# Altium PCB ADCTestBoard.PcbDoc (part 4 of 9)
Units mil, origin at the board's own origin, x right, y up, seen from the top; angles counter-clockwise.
Board outline 11022.62 x 9187 mil, 8 copper layers (TopLayer, InternalPlane1, InternalPlane2, InternalPlane3, InternalPlane4, InternalPlane5, MidLayer1, BottomLayer), stack 103.8 mil thick; 1282 components, 637 nets, 4473 pads, 1306 vias.
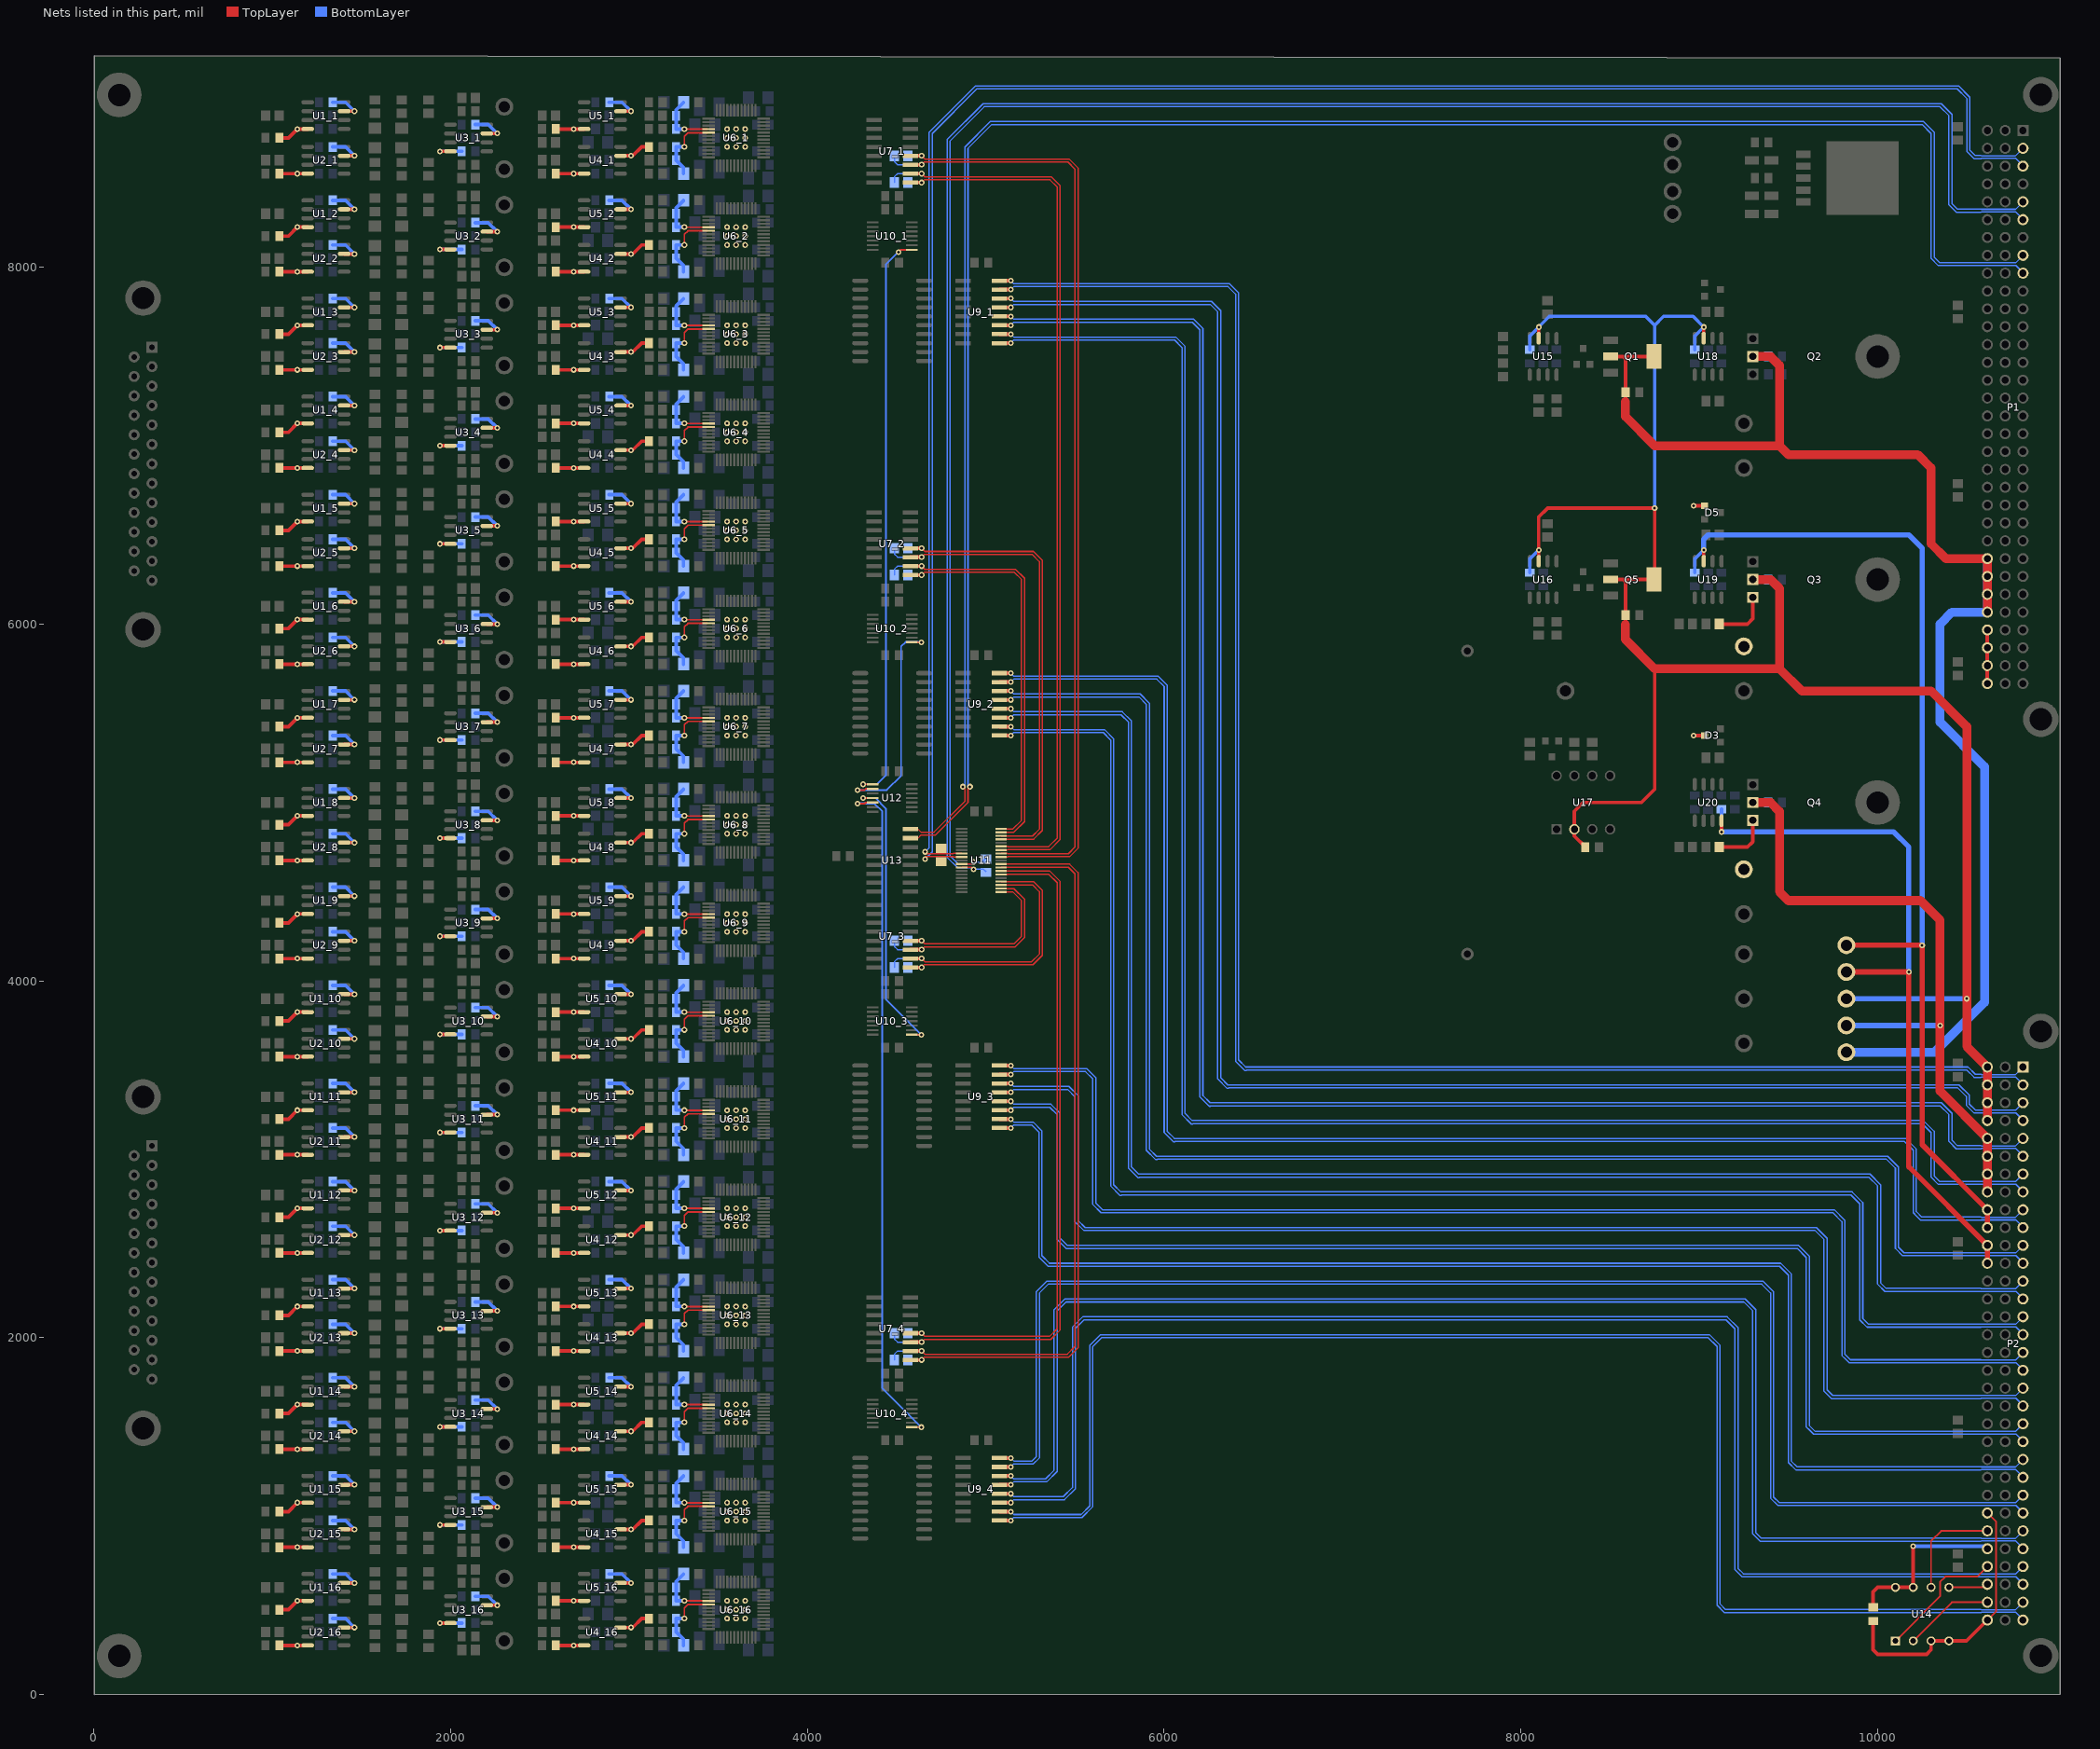
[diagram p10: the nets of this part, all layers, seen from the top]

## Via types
v1: diameter 32, hole 16, TopLayer to BottomLayer, 1306 vias

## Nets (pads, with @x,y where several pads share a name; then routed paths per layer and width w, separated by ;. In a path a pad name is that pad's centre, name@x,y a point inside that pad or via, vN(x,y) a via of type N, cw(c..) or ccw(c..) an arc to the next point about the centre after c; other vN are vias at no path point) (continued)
+15V: C1_1.1 C1_2.1 C1_3.1 C1_4.1 C1_5.1 C1_6.1 C1_7.1 C1_8.1 C1_9.1 C1_10.1 C1_11.1 C1_12.1 C1_13.1 C1_14.1 C1_15.1 C1_16.1 C3_1.1 C3_2.1 C3_3.1 C3_4.1 C3_5.1 C3_6.1 C3_7.1 C3_8.1 C3_9.1 C3_10.1 C3_11.1 C3_12.1 C3_13.1 C3_14.1 C3_15.1 C3_16.1 C19_1.1 C19_2.1 C19_3.1 C19_4.1 C19_5.1 C19_6.1 C19_7.1 C19_8.1 C19_9.1 C19_10.1 C19_11.1 C19_12.1 C19_13.1 C19_14.1 C19_15.1 C19_16.1 C20_1.2 C20_2.2 C20_3.2 C20_4.2 C20_5.2 C20_6.2 C20_7.2 C20_8.2 C20_9.2 C20_10.2 C20_11.2 C20_12.2 C20_13.2 C20_14.2 C20_15.2 C20_16.2 C21_1.2 C21_2.2 C21_3.2 C21_4.2 C21_5.2 C21_6.2 C21_7.2 C21_8.2 C21_9.2 C21_10.2 C21_11.2 C21_12.2 C21_13.2 C21_14.2 C21_15.2 C21_16.2 C22_1.2 C22_2.2 C22_3.2 C22_4.2 C22_5.2 C22_6.2 C22_7.2 C22_8.2 C22_9.2 C22_10.2 C22_11.2 C22_12.2 C22_13.2 C22_14.2 C22_15.2 C22_16.2 C29_1.1 C29_2.1 C29_3.1 C29_4.1 C29_5.1 C29_6.1 C29_7.1 C29_8.1 C29_9.1 C29_10.1 C29_11.1 C29_12.1 C29_13.1 C29_14.1 C29_15.1 C29_16.1 C38_1.1 C38_2.1 C38_3.1 C38_4.1 C38_5.1 C38_6.1 C38_7.1 C38_8.1 C38_9.1 C38_10.1 C38_11.1 C38_12.1 C38_13.1 C38_14.1 C38_15.1 C38_16.1 D5.1 Q3.3 R44.2 TP12.1 U1_1.7 U1_2.7 U1_3.7 U1_4.7 U1_5.7 U1_6.7 U1_7.7 U1_8.7 U1_9.7 U1_10.7 U1_11.7 U1_12.7 U1_13.7 U1_14.7 U1_15.7 U1_16.7 U2_1.7 U2_2.7 U2_3.7 U2_4.7 U2_5.7 U2_6.7 U2_7.7 U2_8.7 U2_9.7 U2_10.7 U2_11.7 U2_12.7 U2_13.7 U2_14.7 U2_15.7 U2_16.7 U3_1.7 U3_2.7 U3_3.7 U3_4.7 U3_5.7 U3_6.7 U3_7.7 U3_8.7 U3_9.7 U3_10.7 U3_11.7 U3_12.7 U3_13.7 U3_14.7 U3_15.7 U3_16.7 U4_1.7 U4_2.7 U4_3.7 U4_4.7 U4_5.7 U4_6.7 U4_7.7 U4_8.7 U4_9.7 U4_10.7 U4_11.7 U4_12.7 U4_13.7 U4_14.7 U4_15.7 U4_16.7 U5_1.7 U5_2.7 U5_3.7 U5_4.7 U5_5.7 U5_6.7 U5_7.7 U5_8.7 U5_9.7 U5_10.7 U5_11.7 U5_12.7 U5_13.7 U5_14.7 U5_15.7 U5_16.7 U6_1.40 U6_2.40 U6_3.40 U6_4.40 U6_5.40 U6_6.40 U6_7.40 U6_8.40 U6_9.40 U6_10.40 U6_11.40 U6_12.40 U6_13.40 U6_14.40 U6_15.40 U6_16.40 | length 21497.4
  TopLayer w10: v1(3310,525) 3310.79,524.21 U6_16.40@3435.63,524.21 ; v1(3310,1075) 3310.79,1074.21 U6_15.40@3435.63,1074.21 ; v1(3310,1625) 3310.79,1624.21 U6_14.40@3435.63,1624.21 ; v1(3310,2175) 3310.79,2174.21 U6_13.40@3435.63,2174.21 ; v1(3310,2725) 3310.79,2724.21 U6_12.40@3435.63,2724.21 ; v1(3310,3275) 3310.79,3274.21 U6_11.40@3435.63,3274.21 ; v1(3310,3825) 3310.79,3824.21 U6_10.40@3435.63,3824.21 ; v1(3310,4375) 3310.79,4374.21 U6_9.40@3435.63,4374.21 ; v1(3310,4925) 3310.79,4924.21 U6_8.40@3435.63,4924.21 ; v1(3310,5475) 3310.79,5474.21 U6_7.40@3435.63,5474.21 ; v1(3310,6025) 3310.79,6024.21 U6_6.40@3435.63,6024.21 ; v1(3310,6575) 3310.79,6574.21 U6_5.40@3435.63,6574.21 ; v1(3310,7125) 3310.79,7124.21 U6_4.40@3435.63,7124.21 ; v1(3310,7675) 3310.79,7674.21 U6_3.40@3435.63,7674.21 ; v1(3310,8225) 3310.79,8224.21 U6_2.40@3435.63,8224.21 ; v1(3310,8775) 3310.79,8774.21 U6_1.40@3435.63,8774.21
  TopLayer w20: U2_16.7@1402.36,375 v1(1460,375) ; U1_16.7@1402.36,625 v1(1460,625) ; U2_15.7@1402.36,925 v1(1460,925) ; U1_15.7@1402.36,1175 v1(1460,1175) ; U2_14.7@1402.36,1475 v1(1460,1475) ; U1_14.7@1402.36,1725 v1(1460,1725) ; U2_13.7@1402.36,2025 v1(1460,2025) ; U1_13.7@1402.36,2275 v1(1460,2275) ; U2_12.7@1402.36,2575 v1(1460,2575) ; U1_12.7@1402.36,2825 v1(1460,2825) ; U2_11.7@1402.36,3125 v1(1460,3125) ; U1_11.7@1402.36,3375 v1(1460,3375) ; U2_10.7@1402.36,3675 v1(1460,3675) ; U1_10.7@1402.36,3925 v1(1460,3925) ; U2_9.7@1402.36,4225 v1(1460,4225) ; U1_9.7@1402.36,4475 v1(1460,4475) ; U2_8.7@1402.36,4775 v1(1460,4775) ; U1_8.7@1402.36,5025 v1(1460,5025) ; U2_7.7@1402.36,5325 v1(1460,5325) ; U1_7.7@1402.36,5575 v1(1460,5575) ; U2_6.7@1402.36,5875 v1(1460,5875) ; U1_6.7@1402.36,6125 v1(1460,6125) ; U2_5.7@1402.36,6425 v1(1460,6425) ; U1_5.7@1402.36,6675 v1(1460,6675) ; U2_4.7@1402.36,6975 v1(1460,6975) ; U1_4.7@1402.36,7225 v1(1460,7225) ; U2_3.7@1402.36,7525 v1(1460,7525) ; U1_3.7@1402.36,7775 v1(1460,7775) ; U2_2.7@1402.36,8075 v1(1460,8075) ; U1_2.7@1402.36,8325 v1(1460,8325) ; U2_1.7@1402.36,8625 v1(1460,8625) ; U1_1.7@1402.36,8875 v1(1460,8875) ; U3_16.7@2202.36,500 v1(2260,500) ; U3_15.7@2202.36,1050 v1(2260,1050) ; U3_14.7@2202.36,1600 v1(2260,1600) ; U3_13.7@2202.36,2150 v1(2260,2150) ; U3_12.7@2202.36,2700 v1(2260,2700) ; U3_11.7@2202.36,3250 v1(2260,3250) ; U3_10.7@2202.36,3800 v1(2260,3800) ; U3_9.7@2202.36,4350 v1(2260,4350) ; U3_8.7@2202.36,4900 v1(2260,4900) ; U3_7.7@2202.36,5450 v1(2260,5450) ; U3_6.7@2202.36,6000 v1(2260,6000) ; U3_5.7@2202.36,6550 v1(2260,6550) ; U3_4.7@2202.36,7100 v1(2260,7100) ; U3_3.7@2202.36,7650 v1(2260,7650) ; U3_2.7@2202.36,8200 v1(2260,8200) ; U3_1.7@2202.36,8750 v1(2260,8750) ; U4_16.7@2952.36,375 3020,375 3070,425 C38_16.1@3111.61,425 ; U5_16.7@2952.36,625 v1(3010,625) ; U4_15.7@2952.36,925 3020,925 3070,975 C38_15.1@3111.61,975 ; U5_15.7@2952.36,1175 v1(3010,1175) ; U4_14.7@2952.36,1475 3020,1475 3070,1525 C38_14.1@3111.61,1525 ; U5_14.7@2952.36,1725 v1(3010,1725) ; U4_13.7@2952.36,2025 3020,2025 3070,2075 C38_13.1@3111.61,2075 ; U5_13.7@2952.36,2275 v1(3010,2275) ; U4_12.7@2952.36,2575 3020,2575 3070,2625 C38_12.1@3111.61,2625 ; U5_12.7@2952.36,2825 v1(3010,2825) ; U4_11.7@2952.36,3125 3020,3125 3070,3175 C38_11.1@3111.61,3175 ; U5_11.7@2952.36,3375 v1(3010,3375) ; U4_10.7@2952.36,3675 3020,3675 3070,3725 C38_10.1@3111.61,3725 ; U5_10.7@2952.36,3925 v1(3010,3925) ; U4_9.7@2952.36,4225 3020,4225 3070,4275 C38_9.1@3111.61,4275 ; U5_9.7@2952.36,4475 v1(3010,4475) ; U4_8.7@2952.36,4775 3020,4775 3070,4825 C38_8.1@3111.61,4825 ; U5_8.7@2952.36,5025 v1(3010,5025) ; U4_7.7@2952.36,5325 3020,5325 3070,5375 C38_7.1@3111.61,5375 ; U5_7.7@2952.36,5575 v1(3010,5575) ; U4_6.7@2952.36,5875 3020,5875 3070,5925 C38_6.1@3111.61,5925 ; U5_6.7@2952.36,6125 v1(3010,6125) ; U4_5.7@2952.36,6425 3020,6425 3070,6475 C38_5.1@3111.61,6475 ; U5_5.7@2952.36,6675 v1(3010,6675) ; U4_4.7@2952.36,6975 3020,6975 3070,7025 C38_4.1@3111.61,7025 ; U5_4.7@2952.36,7225 v1(3010,7225) ; U4_3.7@2952.36,7525 3020,7525 3070,7575 C38_3.1@3111.61,7575 ; U5_3.7@2952.36,7775 v1(3010,7775) ; U4_2.7@2952.36,8075 3020,8075 3070,8125 C38_2.1@3111.61,8125 ; U5_2.7@2952.36,8325 v1(3010,8325) ; U4_1.7@2952.36,8625 3020,8625 3070,8675 C38_1.1@3111.61,8675 ; U5_1.7@2952.36,8875 v1(3010,8875) ; v1(8968.07,6662.4) D5.1@9030.71,6662.4 ; R44.2@9112.4,6000 9270,6000 9300,6030 Q3.3@9300,6150
  BottomLayer w20: C19_16.1@1338.39,425 1410,425 v1(1460,375) ; C1_16.1@1338.39,675 1410,675 v1(1460,625) ; C19_15.1@1338.39,975 1410,975 v1(1460,925) ; C1_15.1@1338.39,1225 1410,1225 v1(1460,1175) ; C19_14.1@1338.39,1525 1410,1525 v1(1460,1475) ; C1_14.1@1338.39,1775 1410,1775 v1(1460,1725) ; C19_13.1@1338.39,2075 1410,2075 v1(1460,2025) ; C1_13.1@1338.39,2325 1410,2325 v1(1460,2275) ; C19_12.1@1338.39,2625 1410,2625 v1(1460,2575) ; C1_12.1@1338.39,2875 1410,2875 v1(1460,2825) ; C19_11.1@1338.39,3175 1410,3175 v1(1460,3125) ; C1_11.1@1338.39,3425 1410,3425 v1(1460,3375) ; C19_10.1@1338.39,3725 1410,3725 v1(1460,3675) ; C1_10.1@1338.39,3975 1410,3975 v1(1460,3925) ; C19_9.1@1338.39,4275 1410,4275 v1(1460,4225) ; C1_9.1@1338.39,4525 1410,4525 v1(1460,4475) ; C19_8.1@1338.39,4825 1410,4825 v1(1460,4775) ; C1_8.1@1338.39,5075 1410,5075 v1(1460,5025) ; C19_7.1@1338.39,5375 1410,5375 v1(1460,5325) ; C1_7.1@1338.39,5625 1410,5625 v1(1460,5575) ; C19_6.1@1338.39,5925 1410,5925 v1(1460,5875) ; C1_6.1@1338.39,6175 1410,6175 v1(1460,6125) ; C19_5.1@1338.39,6475 1410,6475 v1(1460,6425) ; C1_5.1@1338.39,6725 1410,6725 v1(1460,6675) ; C19_4.1@1338.39,7025 1410,7025 v1(1460,6975) ; C1_4.1@1338.39,7275 1410,7275 v1(1460,7225) ; C19_3.1@1338.39,7575 1410,7575 v1(1460,7525) ; C1_3.1@1338.39,7825 1410,7825 v1(1460,7775) ; C19_2.1@1338.39,8125 1410,8125 v1(1460,8075) ; C1_2.1@1338.39,8375 1410,8375 v1(1460,8325) ; C19_1.1@1338.39,8675 1410,8675 v1(1460,8625) ; C1_1.1@1338.39,8925 1410,8925 v1(1460,8875) ; C3_16.1@2138.39,550 2210,550 v1(2260,500) ; C3_15.1@2138.39,1100 2210,1100 v1(2260,1050) ; C3_14.1@2138.39,1650 2210,1650 v1(2260,1600) ; C3_13.1@2138.39,2200 2210,2200 v1(2260,2150) ; C3_12.1@2138.39,2750 2210,2750 v1(2260,2700) ; C3_11.1@2138.39,3300 2210,3300 v1(2260,3250) ; C3_10.1@2138.39,3850 2210,3850 v1(2260,3800) ; C3_9.1@2138.39,4400 2210,4400 v1(2260,4350) ; C3_8.1@2138.39,4950 2210,4950 v1(2260,4900) ; C3_7.1@2138.39,5500 2210,5500 v1(2260,5450) ; C3_6.1@2138.39,6050 2210,6050 v1(2260,6000) ; C3_5.1@2138.39,6600 2210,6600 v1(2260,6550) ; C3_4.1@2138.39,7150 2210,7150 v1(2260,7100) ; C3_3.1@2138.39,7700 2210,7700 v1(2260,7650) ; C3_2.1@2138.39,8250 2210,8250 v1(2260,8200) ; C3_1.1@2138.39,8800 2210,8800 v1(2260,8750) ; C29_16.1@2888.39,675 2960,675 v1(3010,625) ; C29_15.1@2888.39,1225 2960,1225 v1(3010,1175) ; C29_14.1@2888.39,1775 2960,1775 v1(3010,1725) ; C29_13.1@2888.39,2325 2960,2325 v1(3010,2275) ; C29_12.1@2888.39,2875 2960,2875 v1(3010,2825) ; C29_11.1@2888.39,3425 2960,3425 v1(3010,3375) ; C29_10.1@2888.39,3975 2960,3975 v1(3010,3925) ; C29_9.1@2888.39,4525 2960,4525 v1(3010,4475) ; C29_8.1@2888.39,5075 2960,5075 v1(3010,5025) ; C29_7.1@2888.39,5625 2960,5625 v1(3010,5575) ; C29_6.1@2888.39,6175 2960,6175 v1(3010,6125) ; C29_5.1@2888.39,6725 2960,6725 v1(3010,6675) ; C29_4.1@2888.39,7275 2960,7275 v1(3010,7225) ; C29_3.1@2888.39,7825 2960,7825 v1(3010,7775) ; C29_2.1@2888.39,8375 2960,8375 v1(3010,8325) ; C29_1.1@2888.39,8925 2960,8925 v1(3010,8875) ; C20_16.2@3305.12,675 3263.39,633.27 C21_16.2@3263.39,525 v1(3310,525) ; C20_15.2@3305.12,1225 3263.39,1183.27 C21_15.2@3263.39,1075 v1(3310,1075) ; C20_14.2@3305.12,1775 3263.39,1733.27 C21_14.2@3263.39,1625 v1(3310,1625) ; C20_13.2@3305.12,2325 3263.39,2283.27 C21_13.2@3263.39,2175 v1(3310,2175) ; C20_12.2@3305.12,2875 3263.39,2833.27 C21_12.2@3263.39,2725 v1(3310,2725) ; C20_11.2@3305.12,3425 3263.39,3383.27 C21_11.2@3263.39,3275 v1(3310,3275) ; C20_10.2@3305.12,3975 3263.39,3933.27 C21_10.2@3263.39,3825 v1(3310,3825) ; C20_9.2@3305.12,4525 3263.39,4483.27 C21_9.2@3263.39,4375 v1(3310,4375) ; C20_8.2@3305.12,5075 3263.39,5033.27 C21_8.2@3263.39,4925 v1(3310,4925) ; C20_7.2@3305.12,5625 3263.39,5583.27 C21_7.2@3263.39,5475 v1(3310,5475) ; C20_6.2@3305.12,6175 3263.39,6133.27 C21_6.2@3263.39,6025 v1(3310,6025) ; C20_5.2@3305.12,6725 3263.39,6683.27 C21_5.2@3263.39,6575 v1(3310,6575) ; C20_4.2@3305.12,7275 3263.39,7233.27 C21_4.2@3263.39,7125 v1(3310,7125) ; C20_3.2@3305.12,7825 3263.39,7783.27 C21_3.2@3263.39,7675 v1(3310,7675) ; C20_2.2@3305.12,8375 3263.39,8333.27 C21_2.2@3263.39,8225 v1(3310,8225) ; C20_1.2@3305.12,8925 3263.39,8883.27 C21_1.2@3263.39,8775 v1(3310,8775)
  other v1: 3010,375 3010,925 3010,1475 3010,2025 3010,2575 3010,3125 3010,3675 3010,4225 3010,4775 3010,5325 3010,5875 3010,6425 3010,6975 3010,7525 3010,8075 3010,8625
+AV1: C47.2 C54.2 P1.25C P1.26C P1.27C P1.28C Q1.2 Q1.4 Q2.2 TP7.1 | length 7901.1
  TopLayer w20: Q1.2@8502.95,7500 8573.23,7500 8586.61,7486.61 ; 8586.61,7247.6 8586.61,7486.61 ; Q1.4@8747.05,7500 8600,7500 8586.61,7486.61
  TopLayer w50: 8586.61,7247.6 8586.61,7163.39 8750,7000 9450,7000 ; Q2.2@9300,7500 9400,7500 9450,7450 9450,7000 ; P1.28C@10615.41,6067 P1.25C@10615.41,6367 10383,6367 10300,6450 10300,6875 10225,6950 9500,6950 9450,7000
  BottomLayer w20: Q2.2@9300,7500 C54.2@9386.61,7500
  BottomLayer w50: TP7.1@9825,3600 10320,3600 10600,3880 10600,5200 10350,5450 10350,6000 10417,6067 P1.28C@10615.41,6067 P1.25C@10615.41,6367
+AV2: C49.1 C50.2 C52.2 C55.1 C59.2 C80.2 P2.1C P2.2C P2.3C P2.4C Q3.2 Q5.2 Q5.4 TP8.1 U15.7 U16.7 U17.2 U18.7 | length 11662.5
  TopLayer w20: U16.7@8100,6352.36 8100,6600 8150,6650 v1(8750,6650) 8750,6252.95 Q5.4@8747.05,6250 8600,6250 8586.61,6236.61 ; U15.7@8100,7602.36 v1(8100,7665) ; C52.2@8361.61,4750 8300,4811.61 8300,4950 8350,5000 8675,5000 8750,5075 8750,5750 ; Q5.2@8502.95,6250 8573.23,6250 8586.61,6236.61 ; 8586.61,5997.6 8586.61,6236.61 ; U18.7@9025,7602.36 v1(9025,7665)
  TopLayer w50: 8586.61,5997.6 8586.61,5913.39 8750,5750 9450,5750 ; Q3.2@9300,6250 9400,6250 9450,6200 9450,5750 ; P2.4C@10615.41,3217 P2.1C@10615.41,3517 10500,3632.41 10500,5425 10300,5625 9575,5625 9450,5750
  BottomLayer w20: C80.2@8050,6288.39 8050,6365 v1(8100,6415) ; C50.2@8050,7538.39 8050,7615 8160,7725 8700,7725 8750,7675 ; v1(8750,6650) 8750,7675 ; C59.2@8975,7538.39 8975,7615 v1(9025,7665) 8965,7725 8800,7725 8750,7675 ; Q3.2@9300,6250 C55.1@9386.61,6250
  BottomLayer w30: TP8.1@9825,3900 v1(10500,3900)
+AV3: C60.1 P2.9C P2.10C TP9.1 U19.7 | length 5920.7
  TopLayer w20: U19.7@9025,6352.36 v1(9025,6415)
  TopLayer w30: TP9.1@9825,4200 v1(10250,4200) 10250,3082.41 P2.9C@10615.41,2717 P2.10C@10615.41,2617
  BottomLayer w20: C60.1@8975,6288.39 8975,6365 v1(9025,6415)
  BottomLayer w30: v1(9025,6415) 9025,6475 9050,6500 10175,6500 10250,6425 v1(10250,4200)
-15V: C5_1.1 C5_2.1 C5_3.1 C5_4.1 C5_5.1 C5_6.1 C5_7.1 C5_8.1 C5_9.1 C5_10.1 C5_11.1 C5_12.1 C5_13.1 C5_14.1 C5_15.1 C5_16.1 C8_1.1 C8_2.1 C8_3.1 C8_4.1 C8_5.1 C8_6.1 C8_7.1 C8_8.1 C8_9.1 C8_10.1 C8_11.1 C8_12.1 C8_13.1 C8_14.1 C8_15.1 C8_16.1 C10_1.1 C10_2.1 C10_3.1 C10_4.1 C10_5.1 C10_6.1 C10_7.1 C10_8.1 C10_9.1 C10_10.1 C10_11.1 C10_12.1 C10_13.1 C10_14.1 C10_15.1 C10_16.1 C28_1.1 C28_2.1 C28_3.1 C28_4.1 C28_5.1 C28_6.1 C28_7.1 C28_8.1 C28_9.1 C28_10.1 C28_11.1 C28_12.1 C28_13.1 C28_14.1 C28_15.1 C28_16.1 C39_1.1 C39_2.1 C39_3.1 C39_4.1 C39_5.1 C39_6.1 C39_7.1 C39_8.1 C39_9.1 C39_10.1 C39_11.1 C39_12.1 C39_13.1 C39_14.1 C39_15.1 C39_16.1 C40_1.2 C40_2.2 C40_3.2 C40_4.2 C40_5.2 C40_6.2 C40_7.2 C40_8.2 C40_9.2 C40_10.2 C40_11.2 C40_12.2 C40_13.2 C40_14.2 C40_15.2 C40_16.2 C41_1.2 C41_2.2 C41_3.2 C41_4.2 C41_5.2 C41_6.2 C41_7.2 C41_8.2 C41_9.2 C41_10.2 C41_11.2 C41_12.2 C41_13.2 C41_14.2 C41_15.2 C41_16.2 C42_1.2 C42_2.2 C42_3.2 C42_4.2 C42_5.2 C42_6.2 C42_7.2 C42_8.2 C42_9.2 C42_10.2 C42_11.2 C42_12.2 C42_13.2 C42_14.2 C42_15.2 C42_16.2 D3.3 pad.0 Q4.3 R35.2 TP10.1 U1_1.4 U1_2.4 U1_3.4 U1_4.4 U1_5.4 U1_6.4 U1_7.4 U1_8.4 U1_9.4 U1_10.4 U1_11.4 U1_12.4 U1_13.4 U1_14.4 U1_15.4 U1_16.4 U2_1.4 U2_2.4 U2_3.4 U2_4.4 U2_5.4 U2_6.4 U2_7.4 U2_8.4 U2_9.4 U2_10.4 U2_11.4 U2_12.4 U2_13.4 U2_14.4 U2_15.4 U2_16.4 U3_1.4 U3_2.4 U3_3.4 U3_4.4 U3_5.4 U3_6.4 U3_7.4 U3_8.4 U3_9.4 U3_10.4 U3_11.4 U3_12.4 U3_13.4 U3_14.4 U3_15.4 U3_16.4 U4_1.4 U4_2.4 U4_3.4 U4_4.4 U4_5.4 U4_6.4 U4_7.4 U4_8.4 U4_9.4 U4_10.4 U4_11.4 U4_12.4 U4_13.4 U4_14.4 U4_15.4 U4_16.4 U5_1.4 U5_2.4 U5_3.4 U5_4.4 U5_5.4 U5_6.4 U5_7.4 U5_8.4 U5_9.4 U5_10.4 U5_11.4 U5_12.4 U5_13.4 U5_14.4 U5_15.4 U5_16.4 U6_1.41 U6_2.41 U6_3.41 U6_4.41 U6_5.41 U6_6.41 U6_7.41 U6_8.41 U6_9.41 U6_10.41 U6_11.41 U6_12.41 U6_13.41 U6_14.41 U6_15.41 U6_16.41 | length 20296.1
  TopLayer w10: v1(3310,425) 3310,485 3329.53,504.53 U6_16.41@3435.63,504.53 ; v1(3310,975) 3310,1035 3329.53,1054.53 U6_15.41@3435.63,1054.53 ; v1(3310,1525) 3310,1585 3329.53,1604.53 U6_14.41@3435.63,1604.53 ; v1(3310,2075) 3310,2135 3329.53,2154.53 U6_13.41@3435.63,2154.53 ; v1(3310,2625) 3310,2685 3329.53,2704.53 U6_12.41@3435.63,2704.53 ; v1(3310,3175) 3310,3235 3329.53,3254.53 U6_11.41@3435.63,3254.53 ; v1(3310,3725) 3310,3785 3329.53,3804.53 U6_10.41@3435.63,3804.53 ; v1(3310,4275) 3310,4335 3329.53,4354.53 U6_9.41@3435.63,4354.53 ; v1(3310,4825) 3310,4885 3329.53,4904.53 U6_8.41@3435.63,4904.53 ; v1(3310,5375) 3310,5435 3329.53,5454.53 U6_7.41@3435.63,5454.53 ; v1(3310,5925) 3310,5985 3329.53,6004.53 U6_6.41@3435.63,6004.53 ; v1(3310,6475) 3310,6535 3329.53,6554.53 U6_5.41@3435.63,6554.53 ; v1(3310,7025) 3310,7085 3329.53,7104.53 U6_4.41@3435.63,7104.53 ; v1(3310,7575) 3310,7635 3329.53,7654.53 U6_3.41@3435.63,7654.53 ; v1(3310,8125) 3310,8185 3329.53,8204.53 U6_2.41@3435.63,8204.53 ; v1(3310,8675) 3310,8735 3329.53,8754.53 U6_1.41@3435.63,8754.53
  TopLayer w20: C8_16.1@1038.39,275 U2_16.4@1197.64,275 ; C5_16.1@1038.39,475 1090,475 v1(1140,525) U1_16.4@1197.64,525 ; C8_15.1@1038.39,825 U2_15.4@1197.64,825 ; C5_15.1@1038.39,1025 1090,1025 v1(1140,1075) U1_15.4@1197.64,1075 ; C8_14.1@1038.39,1375 U2_14.4@1197.64,1375 ; C5_14.1@1038.39,1575 1090,1575 v1(1140,1625) U1_14.4@1197.64,1625 ; C8_13.1@1038.39,1925 U2_13.4@1197.64,1925 ; C5_13.1@1038.39,2125 1090,2125 v1(1140,2175) U1_13.4@1197.64,2175 ; C8_12.1@1038.39,2475 U2_12.4@1197.64,2475 ; C5_12.1@1038.39,2675 1090,2675 v1(1140,2725) U1_12.4@1197.64,2725 ; C8_11.1@1038.39,3025 U2_11.4@1197.64,3025 ; C5_11.1@1038.39,3225 1090,3225 v1(1140,3275) U1_11.4@1197.64,3275 ; C8_10.1@1038.39,3575 U2_10.4@1197.64,3575 ; C5_10.1@1038.39,3775 1090,3775 v1(1140,3825) U1_10.4@1197.64,3825 ; C8_9.1@1038.39,4125 U2_9.4@1197.64,4125 ; C5_9.1@1038.39,4325 1090,4325 v1(1140,4375) U1_9.4@1197.64,4375 ; C8_8.1@1038.39,4675 U2_8.4@1197.64,4675 ; C5_8.1@1038.39,4875 1090,4875 v1(1140,4925) U1_8.4@1197.64,4925 ; C8_7.1@1038.39,5225 U2_7.4@1197.64,5225 ; C5_7.1@1038.39,5425 1090,5425 v1(1140,5475) U1_7.4@1197.64,5475 ; C8_6.1@1038.39,5775 U2_6.4@1197.64,5775 ; C5_6.1@1038.39,5975 1090,5975 v1(1140,6025) U1_6.4@1197.64,6025 ; C8_5.1@1038.39,6325 U2_5.4@1197.64,6325 ; C5_5.1@1038.39,6525 1090,6525 v1(1140,6575) U1_5.4@1197.64,6575 ; C8_4.1@1038.39,6875 U2_4.4@1197.64,6875 ; C5_4.1@1038.39,7075 1090,7075 v1(1140,7125) U1_4.4@1197.64,7125 ; C8_3.1@1038.39,7425 U2_3.4@1197.64,7425 ; C5_3.1@1038.39,7625 1090,7625 v1(1140,7675) U1_3.4@1197.64,7675 ; C8_2.1@1038.39,7975 U2_2.4@1197.64,7975 ; C5_2.1@1038.39,8175 1090,8175 v1(1140,8225) U1_2.4@1197.64,8225 ; C8_1.1@1038.39,8525 U2_1.4@1197.64,8525 ; C5_1.1@1038.39,8725 1090,8725 v1(1140,8775) U1_1.4@1197.64,8775 ; v1(1940,400) U3_16.4@1997.64,400 ; v1(1940,950) U3_15.4@1997.64,950 ; v1(1940,1500) U3_14.4@1997.64,1500 ; v1(1940,2050) U3_13.4@1997.64,2050 ; v1(1940,2600) U3_12.4@1997.64,2600 ; v1(1940,3150) U3_11.4@1997.64,3150 ; v1(1940,3700) U3_10.4@1997.64,3700 ; v1(1940,4250) U3_9.4@1997.64,4250 ; v1(1940,4800) U3_8.4@1997.64,4800 ; v1(1940,5350) U3_7.4@1997.64,5350 ; v1(1940,5900) U3_6.4@1997.64,5900 ; v1(1940,6450) U3_5.4@1997.64,6450 ; v1(1940,7000) U3_4.4@1997.64,7000 ; v1(1940,7550) U3_3.4@1997.64,7550 ; v1(1940,8100) U3_2.4@1997.64,8100 ; v1(1940,8650) U3_1.4@1997.64,8650 ; C28_16.1@2588.39,275 U4_16.4@2747.64,275 ; C39_16.1@2588.39,525 U5_16.4@2747.64,525 ; C28_15.1@2588.39,825 U4_15.4@2747.64,825 ; C39_15.1@2588.39,1075 U5_15.4@2747.64,1075 ; C28_14.1@2588.39,1375 U4_14.4@2747.64,1375 ; C39_14.1@2588.39,1625 U5_14.4@2747.64,1625 ; C28_13.1@2588.39,1925 U4_13.4@2747.64,1925 ; C39_13.1@2588.39,2175 U5_13.4@2747.64,2175 ; C28_12.1@2588.39,2475 U4_12.4@2747.64,2475 ; C39_12.1@2588.39,2725 U5_12.4@2747.64,2725 ; C28_11.1@2588.39,3025 U4_11.4@2747.64,3025 ; C39_11.1@2588.39,3275 U5_11.4@2747.64,3275 ; C28_10.1@2588.39,3575 U4_10.4@2747.64,3575 ; C39_10.1@2588.39,3825 U5_10.4@2747.64,3825 ; C28_9.1@2588.39,4125 U4_9.4@2747.64,4125 ; C39_9.1@2588.39,4375 U5_9.4@2747.64,4375 ; C28_8.1@2588.39,4675 U4_8.4@2747.64,4675 ; C39_8.1@2588.39,4925 U5_8.4@2747.64,4925 ; C28_7.1@2588.39,5225 U4_7.4@2747.64,5225 ; C39_7.1@2588.39,5475 U5_7.4@2747.64,5475 ; C28_6.1@2588.39,5775 U4_6.4@2747.64,5775 ; C39_6.1@2588.39,6025 U5_6.4@2747.64,6025 ; C28_5.1@2588.39,6325 U4_5.4@2747.64,6325 ; C39_5.1@2588.39,6575 U5_5.4@2747.64,6575 ; C28_4.1@2588.39,6875 U4_4.4@2747.64,6875 ; C39_4.1@2588.39,7125 U5_4.4@2747.64,7125 ; C28_3.1@2588.39,7425 U4_3.4@2747.64,7425 ; C39_3.1@2588.39,7675 U5_3.4@2747.64,7675 ; C28_2.1@2588.39,7975 U4_2.4@2747.64,7975 ; C39_2.1@2588.39,8225 U5_2.4@2747.64,8225 ; C28_1.1@2588.39,8525 U4_1.4@2747.64,8525 ; C39_1.1@2588.39,8775 U5_1.4@2747.64,8775 ; v1(8968.07,5375) D3.3@9030.71,5375 ; R35.2@9112.4,4750 9270,4750 9300,4780 Q4.3@9300,4900
  BottomLayer w20: v1(1940,400) C10_16.1@2061.61,400 ; v1(1940,950) C10_15.1@2061.61,950 ; v1(1940,1500) C10_14.1@2061.61,1500 ; v1(1940,2050) C10_13.1@2061.61,2050 ; v1(1940,2600) C10_12.1@2061.61,2600 ; v1(1940,3150) C10_11.1@2061.61,3150 ; v1(1940,3700) C10_10.1@2061.61,3700 ; v1(1940,4250) C10_9.1@2061.61,4250 ; v1(1940,4800) C10_8.1@2061.61,4800 ; v1(1940,5350) C10_7.1@2061.61,5350 ; v1(1940,5900) C10_6.1@2061.61,5900 ; v1(1940,6450) C10_5.1@2061.61,6450 ; v1(1940,7000) C10_4.1@2061.61,7000 ; v1(1940,7550) C10_3.1@2061.61,7550 ; v1(1940,8100) C10_2.1@2061.61,8100 ; v1(1940,8650) C10_1.1@2061.61,8650 ; C40_16.2@3305.12,275 3305.12,308.27 C41_16.2@3263.39,350 C42_16.2@3263.39,425 v1(3310,425) ; C40_15.2@3305.12,825 3305.12,858.27 C41_15.2@3263.39,900 C42_15.2@3263.39,975 v1(3310,975) ; C40_14.2@3305.12,1375 3305.12,1408.27 C41_14.2@3263.39,1450 C42_14.2@3263.39,1525 v1(3310,1525) ; C40_13.2@3305.12,1925 3305.12,1958.27 C41_13.2@3263.39,2000 C42_13.2@3263.39,2075 v1(3310,2075) ; C40_12.2@3305.12,2475 3305.12,2508.27 C41_12.2@3263.39,2550 C42_12.2@3263.39,2625 v1(3310,2625) ; C40_11.2@3305.12,3025 3305.12,3058.27 C41_11.2@3263.39,3100 C42_11.2@3263.39,3175 v1(3310,3175) ; C40_10.2@3305.12,3575 3305.12,3608.27 C41_10.2@3263.39,3650 C42_10.2@3263.39,3725 v1(3310,3725) ; C40_9.2@3305.12,4125 3305.12,4158.27 C41_9.2@3263.39,4200 C42_9.2@3263.39,4275 v1(3310,4275) ; C40_8.2@3305.12,4675 3305.12,4708.27 C41_8.2@3263.39,4750 C42_8.2@3263.39,4825 v1(3310,4825) ; C40_7.2@3305.12,5225 3305.12,5258.27 C41_7.2@3263.39,5300 C42_7.2@3263.39,5375 v1(3310,5375) ; C40_6.2@3305.12,5775 3305.12,5808.27 C41_6.2@3263.39,5850 C42_6.2@3263.39,5925 v1(3310,5925) ; C40_5.2@3305.12,6325 3305.12,6358.27 C41_5.2@3263.39,6400 C42_5.2@3263.39,6475 v1(3310,6475) ; C40_4.2@3305.12,6875 3305.12,6908.27 C41_4.2@3263.39,6950 C42_4.2@3263.39,7025 v1(3310,7025) ; C40_3.2@3305.12,7425 3305.12,7458.27 C41_3.2@3263.39,7500 C42_3.2@3263.39,7575 v1(3310,7575) ; C40_2.2@3305.12,7975 3305.12,8008.27 C41_2.2@3263.39,8050 C42_2.2@3263.39,8125 v1(3310,8125) ; C40_1.2@3305.12,8525 3305.12,8558.27 C41_1.2@3263.39,8600 C42_1.2@3263.39,8675 v1(3310,8675)
  other v1: 1140,275 2690,275 2690,525 1140,825 2690,825 2690,1075 1140,1375 2690,1375 2690,1625 1140,1925 2690,1925 2690,2175 1140,2475 2690,2475 2690,2725 1140,3025 2690,3025 2690,3275 1140,3575 2690,3575 2690,3825 1140,4125 2690,4125 2690,4375 1140,4675 2690,4675 2690,4925 1140,5225 2690,5225 2690,5475 1140,5775 2690,5775 2690,6025 1140,6325 2690,6325 2690,6575 1140,6875 2690,6875 2690,7125 1140,7425 2690,7425 2690,7675 1140,7975 2690,7975 2690,8225 1140,8525 2690,8525 2690,8775
-AV1: P1.29C P1.30C P1.31C P1.32C | length 300
  TopLayer w20: P1.32C@10615.41,5667 P1.29C@10615.41,5967
-AV2: C65.1 P2.5C P2.6C P2.7C P2.8C Q4.2 TP5.1 | length 3831.5
  TopLayer w50: Q4.2@9300,5000 9400,5000 9450,4950 9450,4500 9500,4450 10240,4450 10350,4340 10350,3382.41 P2.5C@10615.41,3117 P2.8C@10615.41,2817
  BottomLayer w20: Q4.2@9300,5000 C65.1@9386.61,5000
  BottomLayer w30: TP5.1@9825,3750 v1(10350,3750)
-AV3: C64.2 P2.11C P2.12C TP4.1 U20.4 | length 4139.9
  TopLayer w20: v1(9125,4835) U20.4@9125,4897.64
  TopLayer w30: TP4.1@9825,4050 v1(10175,4050) 10175,2957.41 P2.11C@10615.41,2517 P2.12C@10615.41,2417
  BottomLayer w20: v1(9125,4835) C64.2@9125,4961.61
  BottomLayer w30: v1(9125,4835) 10090,4835 10175,4750 v1(10175,4050)
ADCLK1_N: R22_1.1 U7_1.1 U11.33 | length 4908.1
  TopLayer w8: v1(4640,8475) 4655,8490 5360,8490 5400,8450 5400,4800 5352.4,4752.4 5123.07,4752.4 5121.73,4753.74 U11.33@5085.24,4753.74
  TopLayer w20: U7_1.1@4577.36,8475 v1(4640,8475)
  BottomLayer w8: R22_1.1@4562.4,8475 v1(4640,8475)
ADCLK1_P: R22_1.2 U7_1.2 U11.32 | length 5080.2
  TopLayer w8: v1(4640,8525) 4658,8507 5367.04,8507 5417,8457.04 5417,4792.96 5359.44,4735.4 5123.07,4735.4 5121.73,4734.06 U11.32@5085.24,4734.06
  TopLayer w20: U7_1.2@4577.36,8525 v1(4640,8525)
  BottomLayer w8: R22_1.2@4487.6,8475 4487.6,8507.6 4505,8525 v1(4640,8525)
ADCLK2_N: R22_2.1 U7_2.1 U11.38 | length 2230.2
  TopLayer w8: v1(4640,6275) 4655,6290 5100,6290 5160,6290 5200,6250 5200,6203.52 ; U11.38@5085.24,4852.17 5121.73,4852.17 5123.07,4850.82 5150.82,4850.82 5200,4900 5200,6225
  TopLayer w20: U7_2.1@4577.36,6275 v1(4640,6275)
  BottomLayer w8: R22_2.1@4562.4,6275 v1(4640,6275)
ADCLK2_P: R22_2.2 U7_2.2 U11.37 | length 2416.5
  TopLayer w8: v1(4640,6325) 4658,6307 5100,6307 5167.04,6307 5217,6257.04 5217,6196.48 ; U11.37@5085.24,4832.48 5121.73,4832.48 5123.07,4833.82 5157.86,4833.82 5217,4892.96 5217,6232.04
  TopLayer w20: U7_2.2@4577.36,6325 v1(4640,6325)
  BottomLayer w8: R22_2.2@4487.6,6275 4487.6,6307.6 4505,6325 v1(4640,6325)
ADCLK3_N: R22_3.1 U7_3.1 U11.23 | length 1461.9
  TopLayer w8: v1(4640,4075) 4655,4090 5264.04,4090 5317,4142.96 5317,4507.04 5268.49,4555.55 5123.07,4555.55 5121.73,4556.89 U11.23@5085.24,4556.89
  TopLayer w20: U7_3.1@4577.36,4075 v1(4640,4075)
  BottomLayer w8: R22_3.1@4562.4,4075 v1(4640,4075)
ADCLK3_P: R22_3.2 U7_3.2 U11.22 | length 1521.4
  TopLayer w8: v1(4640,4125) 4658,4107 5257,4107 5300,4150 5300,4500 5261.45,4538.55 5123.07,4538.55 5121.73,4537.2 U11.22@5085.24,4537.2
  TopLayer w20: U7_3.2@4577.36,4125 v1(4640,4125)
  BottomLayer w8: R22_3.2@4487.6,4075 4487.6,4107.6 4505,4125 v1(4640,4125)
ADCLK4_N: R22_4.1 U7_4.1 U11.28 | length 4161.2
  TopLayer w8: v1(4640,1875) 4655,1890 5464.04,1890 5517,1942.96 5517,4607.04 5470.07,4653.97 5123.07,4653.97 5121.73,4655.32 U11.28@5085.24,4655.32
  TopLayer w20: U7_4.1@4577.36,1875 v1(4640,1875)
  BottomLayer w8: R22_4.1@4562.4,1875 v1(4640,1875)
ADCLK4_P: R22_4.2 U7_4.2 U11.27 | length 4220.7
  TopLayer w8: v1(4640,1925) 4658,1907 5457,1907 5500,1950 5500,4600 5463.03,4636.97 5123.07,4636.97 5121.73,4635.63 U11.27@5085.24,4635.63
  TopLayer w20: U7_4.2@4577.36,1925 v1(4640,1925)
  BottomLayer w8: R22_4.2@4487.6,1875 4487.6,1907.6 4505,1925 v1(4640,1925)
ADCLK_N: P1.2A R24.1 U11.8 | length 10854.9
  TopLayer w8: v1@4659.84,4713.03 4816.93,4713.03 ; v1(4659.84,4723.18) v1@4670,4713.03 ; 4818.27,4714.37 U11.8@4864.76,4714.37
  BottomLayer w8: v1(4659.84,4723.18) 4683,4746.34 4683,8757.04 4942.96,9017 10453.52,9017 10517,8953.52 10517,8657.04 10548.04,8626 10580,8626 10581,8625 10773.41,8625 P1.2A@10815.41,8667
ADCLK_P: P1.3A R24.2 U11.9 | length 10879.6
  TopLayer w8: v1(4659.84,4683.18) v1@4670,4693.34 ; v1@4659.84,4696.03 4816.93,4696.03 ; 4818.27,4694.68 U11.9@4864.76,4694.68
  BottomLayer w8: v1(4659.84,4683.18) 4700,4723.34 4700,8750 4950,9000 10446.48,9000 10500,8946.48 10500,8650 10541,8609 10580,8609 10581,8610 10775,8610 P1.3A@10820,8565
ADCOUT1_N: P2.1A U9_1.16 | length 10117.6
  TopLayer w20: U9_1.16@5077.36,7925 v1(5140,7925)
  BottomLayer w8: v1(5140,7925) 5156.5,7908.5 6365.54,7908.5 6417,7857.04 6417,3557.04 6457.04,3517 10507.04,3517 10548.04,3476 10580,3476 10581,3475 10773.41,3475 P2.1A@10815.41,3517
ADCOUT1_P: P2.2A U9_1.15 | length 10125.5
  TopLayer w20: U9_1.15@5077.36,7875 v1(5140,7875)
  BottomLayer w8: v1(5140,7875) 5156.5,7891.5 6358.5,7891.5 6400,7850 6400,3550 6452.49,3497.51 6459.53,3497.51 6462.02,3500 10500,3500 10541,3459 10580,3459 10581,3460 10775,3460 P2.2A@10820,3415
ADCOUT2_N: P2.4A U9_1.13 | length 10196.2
  TopLayer w20: U9_1.13@5077.36,7775 v1(5140,7775)
  BottomLayer w8: v1(5140,7775) 5156.5,7791.5 6258.5,7791.5 6300,7750 6300,3450 6352.49,3397.51 6359.53,3397.51 6362.02,3400 10450,3400 10497.51,3352.49 10497.51,3302.49 10541,3259 10580,3259 10581,3260 10775,3260 P2.4A@10820,3215
ADCOUT2_P: P2.3A U9_1.14 | length 10188.3
  TopLayer w20: U9_1.14@5077.36,7825 v1(5140,7825)
  BottomLayer w8: v1(5140,7825) 5156.5,7808.5 6265.54,7808.5 6317,7757.04 6317,3457.04 6357.04,3417 10457.04,3417 10514.51,3359.53 10514.51,3309.53 10548.04,3276 10580,3276 10581,3275 10773.41,3275 P2.3A@10815.41,3317
ADCOUT3_N: P2.5A U9_1.12 | length 10288.3
  TopLayer w20: U9_1.12@5077.36,7725 v1(5140,7725)
  BottomLayer w8: v1(5140,7725) 5156.5,7708.5 6165.54,7708.5 6217,7657.04 6217,3357.04 6257.04,3317 10357.04,3317 10417,3257.04 10417,3107.04 10448.04,3076 10580,3076 10581,3075 10773.41,3075 P2.5A@10815.41,3117
ADCOUT3_P: P2.6A U9_1.11 | length 10296.2
  TopLayer w20: U9_1.11@5077.36,7675 v1(5140,7675)
  BottomLayer w8: v1(5140,7675) 5156.5,7691.5 6158.5,7691.5 6200,7650 6200,3350 6252.49,3297.51 6259.53,3297.51 6262.02,3300 10350,3300 10400,3250 10400,3100 10441,3059 10580,3059 10581,3060 10775,3060 P2.6A@10820,3015
ADCOUT4_N: P2.8A U9_1.9 | length 10396.2
  TopLayer w20: U9_1.9@5077.36,7575 v1(5140,7575)
  BottomLayer w8: v1(5140,7575) 5156.5,7591.5 6058.5,7591.5 6100,7550 6100,3250 6152.49,3197.51 6159.53,3197.51 6162.02,3200 10250,3200 10300,3150 10300,2900 10341,2859 10580,2859 10581,2860 10775,2860 P2.8A@10820,2815
ADCOUT4_P: P2.7A U9_1.10 | length 10388.3
  TopLayer w20: U9_1.10@5077.36,7625 v1(5140,7625)
  BottomLayer w8: v1(5140,7625) 5156.5,7608.5 6065.54,7608.5 6117,7557.04 6117,3257.04 6157.04,3217 10257.04,3217 10317,3157.04 10317,2907.04 10348.04,2876 10580,2876 10581,2875 10773.41,2875 P2.7A@10815.41,2917
ADCOUT5_N: P2.9A U9_2.16 | length 8688.3
  TopLayer w20: U9_2.16@5077.36,5725 v1(5140,5725)
  BottomLayer w8: v1(5140,5725) 5156.5,5708.5 5965.54,5708.5 6017,5657.04 6017,3157.04 6057.04,3117 10157.04,3117 10217,3057.04 10217,2707.04 10248.04,2676 10580,2676 10581,2675 10773.41,2675 P2.9A@10815.41,2717
ADCOUT5_P: P2.10A U9_2.15 | length 8696.2
  TopLayer w20: U9_2.15@5077.36,5675 v1(5140,5675)
  BottomLayer w8: v1(5140,5675) 5156.5,5691.5 5958.5,5691.5 6000,5650 6000,3150 6052.49,3097.51 6059.53,3097.51 6062.02,3100 10150,3100 10200,3050 10200,2700 10220,2680 10241,2659 10580,2659 10581,2660 10775,2660 P2.10A@10820,2615
ADCOUT6_N: P2.12A U9_2.13 | length 8796.2
  TopLayer w20: U9_2.13@5077.36,5575 v1(5140,5575)
  BottomLayer w8: v1(5140,5575) 5156.5,5591.5 5858.5,5591.5 5900,5550 5900,3050 5952.49,2997.51 5959.53,2997.51 5962.02,3000 10050,3000 10100,2950 10100,2500 10141,2459 10580,2459 10581,2460 10775,2460 P2.12A@10820,2415
ADCOUT6_P: P2.11A U9_2.14 | length 8788.3
  TopLayer w20: U9_2.14@5077.36,5625 v1(5140,5625)
  BottomLayer w8: v1(5140,5625) 5156.5,5608.5 5865.54,5608.5 5917,5557.04 5917,3057.04 5957.04,3017 10057.04,3017 10117,2957.04 10117,2507.04 10148.04,2476 10580,2476 10581,2475 10773.41,2475 P2.11A@10815.41,2517
ADCOUT7_N: P2.13A U9_2.12 | length 8888.3
  TopLayer w20: U9_2.12@5077.36,5525 v1(5140,5525)
  BottomLayer w8: v1(5140,5525) 5156.5,5508.5 5765.54,5508.5 5817,5457.04 5817,2957.04 5857.04,2917 9957.04,2917 10017,2857.04 10017,2307.04 10048.04,2276 10580,2276 10581,2275 10773.41,2275 P2.13A@10815.41,2317
ADCOUT7_P: P2.14A U9_2.11 | length 8896.2
  TopLayer w20: U9_2.11@5077.36,5475 v1(5140,5475)
  BottomLayer w8: v1(5140,5475) 5156.5,5491.5 5758.5,5491.5 5800,5450 5800,2950 5852.49,2897.51 5859.53,2897.51 5862.02,2900 9950,2900 10000,2850 10000,2300 10041,2259 10580,2259 10581,2260 10775,2260 P2.14A@10820,2215
ADCOUT8_N: P2.16A U9_2.9 | length 8996.2
  TopLayer w20: U9_2.9@5077.36,5375 v1(5140,5375)
  BottomLayer w8: v1(5140,5375) 5156.5,5391.5 5658.5,5391.5 5700,5350 5700,2850 5752.49,2797.51 5759.53,2797.51 5762.02,2800 9850,2800 9900,2750 9900,2100 9941,2059 10580,2059 10581,2060 10775,2060 P2.16A@10820,2015
ADCOUT8_P: P2.15A U9_2.10 | length 8988.3
  TopLayer w20: U9_2.10@5077.36,5425 v1(5140,5425)
  BottomLayer w8: v1(5140,5425) 5156.5,5408.5 5665.54,5408.5 5717,5357.04 5717,2857.04 5757.04,2817 9857.04,2817 9917,2757.04 9917,2107.04 9948.04,2076 10580,2076 10581,2075 10773.41,2075 P2.15A@10815.41,2117
ADCOUT9_N: P2.17A U9_3.16 | length 7290.3
  TopLayer w20: U9_3.16@5077.36,3525 v1(5140,3525)
  BottomLayer w8: v1(5140,3525) 5156.5,3508.5 5565.54,3508.5 5617,3457.04 5617,2753.52 5653.52,2717 9757.04,2717 9817,2657.04 9817,1907.04 9848.04,1876 10580,1876 10581,1875 10773.41,1875 P2.17A@10815.41,1917
ADCOUT9_P: P2.18A U9_3.15 | length 7296.2
  TopLayer w20: U9_3.15@5077.36,3475 v1(5140,3475)
  BottomLayer w8: v1(5140,3475) 5156.5,3491.5 5558.5,3491.5 5600,3450 5600,2746.48 5646.48,2700 9750,2700 9800,2650 9800,1900 9820,1880 9841,1859 10580,1859 10581,1860 10775,1860 P2.18A@10820,1815
ADCOUT10_N: P2.20A U9_3.13 | length 7394.1
  TopLayer w20: U9_3.13@5077.36,3375 v1(5140,3375)
  BottomLayer w8: v1(5140,3375) 5156.5,3391.5 5458.5,3391.5 5500,3350 5500,2650 5550,2600 9650,2600 9700,2550 9700,1700 9720,1680 9741,1659 10580,1659 10581,1660 10775,1660 P2.20A@10820,1615
ADCOUT10_P: P2.19A U9_3.14 | length 7388.3
  TopLayer w20: U9_3.14@5077.36,3425 v1(5140,3425)
  BottomLayer w8: v1(5140,3425) 5156.5,3408.5 5465.54,3408.5 5517,3357.04 5517,2657.04 5557.04,2617 9657.04,2617 9717,2557.04 9717,1707.04 9748.04,1676 10580,1676 10581,1675 10773.41,1675 P2.19A@10815.41,1717
ADCOUT11_N: P2.21A U9_3.12 | length 7488.3
  TopLayer w20: U9_3.12@5077.36,3325 v1(5140,3325)
  BottomLayer w8: v1(5140,3325) 5156.5,3308.5 5365.54,3308.5 5417,3257.04 5417,2557.04 5457.04,2517 9557.04,2517 9617,2457.04 9617,1507.04 9648.04,1476 10580,1476 10581,1475 10773.41,1475 P2.21A@10815.41,1517
ADCOUT11_P: P2.22A U9_3.11 | length 7494.1
  TopLayer w20: U9_3.11@5077.36,3275 v1(5140,3275)
  BottomLayer w8: v1(5140,3275) 5156.5,3291.5 5358.5,3291.5 5400,3250 5400,2550 5450,2500 5500,2500 9550,2500 9600,2450 9600,1500 9620,1480 9641,1459 10580,1459 10581,1460 10775,1460 P2.22A@10820,1415
ADCOUT12_N: P2.24A U9_3.9 | length 7594.1
  TopLayer w20: U9_3.9@5077.36,3175 v1(5140,3175)
  BottomLayer w8: v1(5140,3175) 5156.5,3191.5 5258.5,3191.5 5297.51,3152.49 5297.51,2452.49 5350,2400 9450,2400 9500,2350 9500,1300 9541,1259 10580,1259 10581,1260 10775,1260 P2.24A@10820,1215
ADCOUT12_P: P2.23A U9_3.10 | length 7588.3
  TopLayer w20: U9_3.10@5077.36,3225 v1(5140,3225)
  BottomLayer w8: v1(5140,3225) 5156.5,3208.5 5265.54,3208.5 5314.51,3159.53 5314.51,2459.53 5357.04,2417 9457.04,2417 9517,2357.04 9517,1307.04 9548.04,1276 10580,1276 10581,1275 10773.41,1275 P2.23A@10815.41,1317
ADCOUT13_N: P2.25A U9_4.16 | length 7910
  TopLayer w20: U9_4.16@5077.36,1325 v1(5140,1325)
  BottomLayer w8: v1(5140,1325) 5156.5,1308.5 5259.46,1308.5 5283,1332.04 5283,2257.04 5342.96,2317 7000,2317 9357.04,2317 9417,2257.04 9417,1107.04 9448.04,1076 10580,1076 10581,1075 10773.41,1075 P2.25A@10815.41,1117
ADCOUT13_P: P2.26A U9_4.15 | length 7915.8
  TopLayer w20: U9_4.15@5077.36,1275 v1(5140,1275)
  BottomLayer w8: v1(5140,1275) 5156.5,1291.5 5266.5,1291.5 5300,1325 5300,2250 5350,2300 7000,2300 9350,2300 9400,2250 9400,1100 9441,1059 10580,1059 10581,1060 10775,1060 P2.26A@10820,1015
ADCOUT14_N: P2.28A U9_4.13 | length 8001.2
  TopLayer w20: U9_4.13@5077.36,1175 v1(5140,1175)
  BottomLayer w8: v1(5140,1175) 5156.5,1191.5 5341.5,1191.5 5400,1250 5400,2150 5450,2200 7000,2200 9250,2200 9300,2150 9300,900 9341,859 10580,859 10581,860 10775,860 P2.28A@10820,815
ADCOUT14_P: P2.27A U9_4.14 | length 7995.3
  TopLayer w20: U9_4.14@5077.36,1225 v1(5140,1225)
  BottomLayer w8: v1(5140,1225) 5156.5,1208.5 5334.46,1208.5 5383,1257.04 5383,2157.04 5442.96,2217 7000,2217 9257.04,2217 9317,2157.04 9317,907.04 9348.04,876 10580,876 10581,875 10773.41,875 P2.27A@10815.41,917
ADCOUT15_N: P2.29A U9_4.12 | length 8095.3
  TopLayer w20: U9_4.12@5077.36,1125 v1(5140,1125)
  BottomLayer w8: v1(5140,1125) 5156.5,1108.5 5434.46,1108.5 5485.49,1159.53 5485.49,2059.53 5542.96,2117 9157.04,2117 9217,2057.04 9217,707.04 9248.04,676 10580,676 10581,675 10773.41,675 P2.29A@10815.41,717
ADCOUT15_P: P2.30A U9_4.11 | length 8101.2
  TopLayer w20: U9_4.11@5077.36,1075 v1(5140,1075)
  BottomLayer w8: v1(5140,1075) 5156.5,1091.5 5441.5,1091.5 5502.49,1152.49 5502.49,2052.49 5550,2100 9150,2100 9200,2050 9200,700 9241,659 10580,659 10581,660 10775,660 P2.30A@10820,615
ADCOUT16_N: P2.32A U9_4.9 | length 8199.5
  TopLayer w20: U9_4.9@5077.36,975 v1(5140,975)
  BottomLayer w8: v1(5140,975) 5156.5,991.5 5538.67,991.5 5600,1052.83 5600,1200 5600,1950 5650,2000 9050,2000 9100,1950 9100,500 9141,459 10580,459 10581,460 10775,460 P2.32A@10820,415
ADCOUT16_P: P2.31A U9_4.10 | length 8195.3
  TopLayer w20: U9_4.10@5077.36,1025 v1(5140,1025)
  BottomLayer w8: v1(5140,1025) 5156.5,1008.5 5534.46,1008.5 5583,1057.04 5583,1957.04 5642.96,2017 9057.04,2017 9117,1957.04 9117,507.04 9148.04,476 10580,476 10581,475 10773.41,475 P2.31A@10815.41,517
BUSY1: U10_1.8 U12.1 | length 3244.9
  TopLayer w10: v1(4311.77,5101.77) U12.1@4365.75,5101.77 ; v1(4510,8085) 4523.23,8098.23 U10_1.8@4584.25,8098.23
  BottomLayer w10: v1(4311.77,5101.77) 4390,5101.77 4440,5151.77 4440,8015 v1(4510,8085)
BUSY2: U10_2.8 U12.2 | length 1272.1
  TopLayer w10: v1(4280,5070) 4320,5070 4326.18,5076.18 U12.2@4365.75,5076.18 ; U10_2.8@4584.25,5898.23 v1(4639.41,5898.23)
  BottomLayer w10: v1(4280,5070) 4445,5070 4525,5150 4525,5875 4550,5900 4637.64,5900 v1(4639.41,5898.23)
BUSY3: U10_3.8 U12.4 | length 1609.9
  TopLayer w10: v1(4311.77,5025) U12.4@4365.75,5025 ; U10_3.8@4584.25,3698.23 v1(4638.23,3698.23)
  BottomLayer w10: v1(4311.77,5025) 4380,5025 4440,4965 4440,3896.46 v1(4638.23,3698.23)
BUSY4: U10_4.8 U12.5 | length 3882.4
  TopLayer w10: v1(4280,4993.23) 4320,4993.23 4326.18,4999.41 U12.5@4365.75,4999.41 ; U10_4.8@4584.25,1498.23 v1(4638.23,1498.23)
  BottomLayer w10: v1(4280,4993.23) 4376.77,4993.23 4420,4950 4420,1716.46 v1(4638.23,1498.23) ; v1@4280,4995 4320,4995
BUSY_N: P1.8A U13.16 | length 10819.6
  TopLayer w8: U13.16@4577.36,4850 4620,4850 4636.5,4833.5 4709.46,4833.5 4883,5007.04 4883,5077 v1(4871.5,5088.5)
  BottomLayer w8: v1(4871.5,5088.5) 4883,5100 ; v1@4883,5088.5 4883,8674.2 5025.8,8817 10257.04,8817 10317,8757.04 10317,8057.04 10348.04,8026 10580,8026 10581,8025 10773.41,8025 P1.8A@10815.41,8067
BUSY_P: P1.9A U13.15 | length 10825.4
  TopLayer w8: U13.15@4577.36,4800 4620,4800 4636.5,4816.5 4716.5,4816.5 4900,5000 4900,5077 v1(4911.5,5088.5)
  BottomLayer w8: v1@4900,5088.5 4900,8667.16 5032.84,8800 10250,8800 10300,8750 10300,8050 10341,8009 10580,8009 10581,8010 10775,8010 P1.9A@10820,7965 ; 4900,5100 v1(4911.5,5088.5)
CFG_CLK: P2.27C U14.6 | length 584
  TopLayer w10: U14.6@10300,615 10300,860 10357,917 P2.27C@10615.41,917
CFG_CS: P2.29C U14.1 | length 735
  TopLayer w10: U14.1@10100,300 10350,550 10350,630 10380,660 10558.41,660 P2.29C@10615.41,717
CFG_GND: C85.2 P2.26C P2.32C U14.3 U14.4 | length 1562.3
  TopLayer w10: P2.32C@10615.41,417 10665,466.59 10665,967.41 P2.26C@10615.41,1017
  TopLayer w20: C85.2@9975,411.61 9975,250 10000,225 10275,225 10300,250 U14.3@10300,300 U14.4@10400,300 10498.41,300 P2.32C@10615.41,417
CFG_SI: P2.30C U14.5 | length 222.5
  TopLayer w10: U14.5@10400,600 10598.41,600 P2.30C@10615.41,617
CFG_SO: P2.31C U14.2 | length 529.3
  TopLayer w10: U14.2@10200,300 10417,517 P2.31C@10615.41,517 P2.31C@10598.41,500
CFG_VCC: C85.1 P2.28C U14.7 U14.8 | length 972.8
  TopLayer w20: C85.1@9975,488.39 9975,575 10000,600 U14.8@10100,600 U14.7@10200,600 v1(10200,830)
  BottomLayer w20: v1(10200,830) 10602.41,830 P2.28C@10615.41,817
CONV1_N: R23_1.2 U7_1.3 U11.31 | length 5368.3
  TopLayer w8: v1(4640,8575) 4655,8590 5460,8590 5500,8550 5500,4750 5463.03,4713.03 5123.07,4713.03 5121.73,4714.37 U11.31@5085.24,4714.37
  TopLayer w20: U7_1.3@4577.36,8575 v1(4640,8575)
  BottomLayer w8: R23_1.2@4487.6,8625 4487.6,8592.4 4505,8575 v1(4640,8575)
CONV1_P: R23_1.1 U7_1.4 U11.30 | length 5311.2
  TopLayer w8: v1(4640,8625) 4658,8607 5467.04,8607 5517,8557.04 5517,4742.96 5470.07,4696.03 5123.07,4696.03 5121.73,4694.68 U11.30@5085.24,4694.68
  TopLayer w20: U7_1.4@4577.36,8625 v1(4640,8625)
  BottomLayer w8: R23_1.1@4562.4,8625 v1(4640,8625)
CONV2_N: R23_2.2 U7_2.3 U11.36 | length 2668.9
  TopLayer w8: v1(4640,6375) 4655,6390 5260,6390 5300,6350 5300,4850 5261.45,4811.45 5123.07,4811.45 5121.73,4812.8 U11.36@5085.24,4812.8
  TopLayer w20: U7_2.3@4577.36,6375 v1(4640,6375)
  BottomLayer w8: R23_2.2@4487.6,6425 4487.6,6392.4 4505,6375 v1(4640,6375)
CONV2_P: R23_2.1 U7_2.4 U11.35 | length 2611.9
  TopLayer w8: v1(4640,6425) 4658,6407 5267.04,6407 5317,6357.04 5317,4842.96 5268.49,4794.45 5123.07,4794.45 5121.73,4793.11 U11.35@5085.24,4793.11
  TopLayer w20: U7_2.4@4577.36,6425 v1(4640,6425)
  BottomLayer w8: R23_2.1@4562.4,6425 v1(4640,6425)
CONV3_N: R23_3.2 U7_3.3 U11.21 | length 1284.4
  TopLayer w8: v1(4640,4175) 4655,4190 5164.04,4190 5217,4242.96 5217,4403.52 ; U11.21@5085.24,4517.52 5121.73,4517.52 5123.07,4516.18 5157.86,4516.18 5217,4457.04 5217,4350
  TopLayer w20: U7_3.3@4577.36,4175 v1(4640,4175)
  BottomLayer w8: R23_3.2@4487.6,4225 4487.6,4192.4 4505,4175 v1(4640,4175)
CONV3_P: R23_3.1 U7_3.4 U11.20 | length 1107.7
  TopLayer w8: v1(4640,4225) 4658,4207 5157,4207 5200,4250 5200,4396.48 ; U11.20@5085.24,4497.83 5121.73,4497.83 5123.07,4499.18 5150.82,4499.18 5200,4450 5200,4350
  TopLayer w20: U7_3.4@4577.36,4225 v1(4640,4225)
  BottomLayer w8: R23_3.1@4562.4,4225 v1(4640,4225)
CONV4_N: R23_4.2 U7_4.3 U11.26 | length 3958.8
  TopLayer w8: v1(4640,1975) 4655,1990 5364.04,1990 5417,2042.96 5417,4503.52 ; U11.26@5085.24,4615.94 5121.73,4615.94 5123.07,4614.6 5359.44,4614.6 5417,4557.04 5417,4475
  TopLayer w20: U7_4.3@4577.36,1975 v1(4640,1975)
  BottomLayer w8: R23_4.2@4487.6,2025 4487.6,1992.4 4505,1975 v1(4640,1975)
CONV4_P: R23_4.1 U7_4.4 U11.25 | length 3782
  TopLayer w8: v1(4640,2025) 4658,2007 5357,2007 5400,2050 5400,4496.48 ; U11.25@5085.24,4596.26 5121.73,4596.26 5123.07,4597.6 5352.4,4597.6 5400,4550 5400,4475
  TopLayer w20: U7_4.4@4577.36,2025 v1(4640,2025)
  BottomLayer w8: R23_4.1@4562.4,2025 v1(4640,2025)
CONV_N: P1.6A R25.2 U11.11 | length 10967.1
  TopLayer w8: U11.11@4864.76,4655.32 4920.87,4655.32 v1(4931.03,4665.47)
  BottomLayer w8: R25.2@5000,4687.4 4978.07,4665.47 v1(4931.03,4665.47) 4920.56,4655 4845,4655 4800,4700 4800,8708.58 4991.42,8900 10350,8900 10400,8850 10400,8350 10441,8309 10580,8309 10581,8310 10775,8310 P1.6A@10820,8265
CONV_P: P1.5A R25.1 U11.12 | length 11014.7
  TopLayer w8: U11.12@4864.76,4635.63 4920.87,4635.63 v1(4931.03,4625.47)
  BottomLayer w8: R25.1@5000,4612.6 4987.13,4625.47 v1(4931.03,4625.47) 4921.5,4635 4840.96,4635 4783,4692.96 4783,8715.62 4984.38,8917 10357.04,8917 10417,8857.04 10417,8357.04 10448.04,8326 10580,8326 10581,8325 10773.41,8325 P1.5A@10815.41,8367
